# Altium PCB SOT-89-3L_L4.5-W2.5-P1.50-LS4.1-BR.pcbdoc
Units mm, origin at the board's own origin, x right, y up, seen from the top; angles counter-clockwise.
Board outline 18.08 x 17.35 mm, 2 copper layers (Top Layer, Bottom Layer), stack 0 mm thick; 1 components, 0 nets, 3 pads, 0 vias.
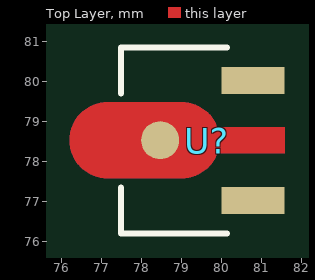
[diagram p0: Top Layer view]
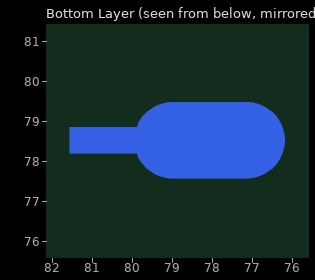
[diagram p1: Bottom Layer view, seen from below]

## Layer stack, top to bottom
Top Layer: signal copper (thickness not stored)
Bottom Layer: signal copper (thickness not stored)

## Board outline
87.927,69.85 69.85,69.85 69.85,87.202 87.927,87.202

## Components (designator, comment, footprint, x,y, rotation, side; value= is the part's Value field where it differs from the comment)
U? "" SOT-89-3L_L4.5-W2.5-P1.50-LS4.1-BR 79.433,78.526 r0 top

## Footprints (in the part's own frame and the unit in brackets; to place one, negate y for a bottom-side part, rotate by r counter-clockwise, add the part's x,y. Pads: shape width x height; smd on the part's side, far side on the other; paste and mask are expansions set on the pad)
SOT-89-3L_L4.5-W2.5-P1.50-LS4.1-BR [mm]
  rect 1.575x0.672 smd: 1(1.356,-1.5) 3(1.356,1.5)
  round 0.95 smd: 2(-0.966,0.009)
  Top Layer region: -2.283,0.959 -0.429,0.959 -0.384,0.958 -0.34,0.955 -0.296,0.949 -0.252,0.942 -0.208,0.933 -0.165,0.921 -0.123,0.908 -0.081,0.893 -0.04,0.875 0,0.856 0.04,0.835 0.078,0.812 0.115,0.788 0.151,0.761 0.185,0.733 0.219,0.704 0.251,0.673 0.281,0.64 0.31,0.606 0.337,0.571 0.362,0.534 0.386,0.497 0.408,0.458 0.428,0.418 0.447,0.339 2.144,0.339 2.144,-0.321 0.447,-0.321 0.428,-0.401 0.408,-0.44 0.386,-0.479 0.362,-0.517 0.337,-0.553 0.31,-0.588 0.281,-0.622 0.251,-0.655 0.219,-0.686 0.185,-0.716 0.151,-0.744 0.115,-0.77 0.078,-0.795 0.04,-0.818 0,-0.839 -0.04,-0.858 -0.081,-0.875 -0.123,-0.89 -0.165,-0.904 -0.208,-0.915 -0.252,-0.925 -0.296,-0.932 -0.34,-0.937 -0.384,-0.94 -0.429,-0.941 -2.283,-0.941 -2.328,-0.94 -2.372,-0.937 -2.416,-0.932 -2.46,-0.925 -2.504,-0.915 -2.547,-0.904 -2.589,-0.89 -2.631,-0.875 -2.672,-0.858 -2.713,-0.839 -2.752,-0.818 -2.79,-0.795 -2.827,-0.77 -2.863,-0.744 -2.898,-0.716 -2.931,-0.686 -2.963,-0.655 -2.993,-0.622 -3.022,-0.588 -3.049,-0.553 -3.075,-0.517 -3.098,-0.479 -3.12,-0.44 -3.141,-0.401 -3.159,-0.36 -3.175,-0.318 -3.189,-0.276 -3.202,-0.233 -3.212,-0.19 -3.22,-0.146 -3.227,-0.102 -3.231,-0.058 -3.233,-0.013 -3.233,0.031 -3.231,0.076 -3.227,0.12 -3.22,0.164 -3.212,0.208 -3.202,0.251 -3.189,0.294 -3.175,0.336 -3.159,0.377 -3.141,0.418 -3.12,0.458 -3.098,0.497 -3.075,0.534 -3.049,0.571 -3.022,0.606 -2.993,0.64 -2.963,0.673 -2.931,0.704 -2.898,0.733 -2.863,0.761 -2.827,0.788 -2.79,0.812 -2.752,0.835 -2.713,0.856 -2.672,0.875 -2.631,0.893 -2.589,0.908 -2.547,0.921 -2.504,0.933 -2.46,0.942 -2.416,0.949 -2.372,0.955 -2.328,0.958
  Bottom Layer region: -2.283,0.959 -0.429,0.959 -0.384,0.958 -0.34,0.955 -0.296,0.949 -0.252,0.942 -0.208,0.933 -0.165,0.921 -0.123,0.908 -0.081,0.893 -0.04,0.875 0,0.856 0.04,0.835 0.078,0.812 0.115,0.788 0.151,0.761 0.185,0.733 0.219,0.704 0.251,0.673 0.281,0.64 0.31,0.606 0.337,0.571 0.362,0.534 0.386,0.497 0.408,0.458 0.428,0.418 0.447,0.339 2.144,0.339 2.144,-0.321 0.447,-0.321 0.428,-0.401 0.408,-0.44 0.386,-0.479 0.362,-0.517 0.337,-0.553 0.31,-0.588 0.281,-0.622 0.251,-0.655 0.219,-0.686 0.185,-0.716 0.151,-0.744 0.115,-0.77 0.078,-0.795 0.04,-0.818 0,-0.839 -0.04,-0.858 -0.081,-0.875 -0.123,-0.89 -0.165,-0.904 -0.208,-0.915 -0.252,-0.925 -0.296,-0.932 -0.34,-0.937 -0.384,-0.94 -0.429,-0.941 -2.283,-0.941 -2.328,-0.94 -2.372,-0.937 -2.416,-0.932 -2.46,-0.925 -2.504,-0.915 -2.547,-0.904 -2.589,-0.89 -2.631,-0.875 -2.672,-0.858 -2.713,-0.839 -2.752,-0.818 -2.79,-0.795 -2.827,-0.77 -2.863,-0.744 -2.898,-0.716 -2.931,-0.686 -2.963,-0.655 -2.993,-0.622 -3.022,-0.588 -3.049,-0.553 -3.075,-0.517 -3.098,-0.479 -3.12,-0.44 -3.141,-0.401 -3.159,-0.36 -3.175,-0.318 -3.189,-0.276 -3.202,-0.233 -3.212,-0.19 -3.22,-0.146 -3.227,-0.102 -3.231,-0.058 -3.233,-0.013 -3.233,0.031 -3.231,0.076 -3.227,0.12 -3.22,0.164 -3.212,0.208 -3.202,0.251 -3.189,0.294 -3.175,0.336 -3.159,0.377 -3.141,0.418 -3.12,0.458 -3.098,0.497 -3.075,0.534 -3.049,0.571 -3.022,0.606 -2.993,0.64 -2.963,0.673 -2.931,0.704 -2.898,0.733 -2.863,0.761 -2.827,0.788 -2.79,0.812 -2.752,0.835 -2.713,0.856 -2.672,0.875 -2.631,0.893 -2.589,0.908 -2.547,0.921 -2.504,0.933 -2.46,0.942 -2.416,0.949 -2.372,0.955 -2.328,0.958
  Multi-Layer region: -2.283,0.959 -0.429,0.959 -0.384,0.958 -0.34,0.955 -0.296,0.949 -0.252,0.942 -0.208,0.933 -0.165,0.921 -0.123,0.908 -0.081,0.893 -0.04,0.875 0,0.856 0.04,0.835 0.078,0.812 0.115,0.788 0.151,0.761 0.185,0.733 0.219,0.704 0.251,0.673 0.281,0.64 0.31,0.606 0.337,0.571 0.362,0.534 0.386,0.497 0.408,0.458 0.428,0.418 0.447,0.339 2.144,0.339 2.144,-0.321 0.447,-0.321 0.428,-0.401 0.408,-0.44 0.386,-0.479 0.362,-0.517 0.337,-0.553 0.31,-0.588 0.281,-0.622 0.251,-0.655 0.219,-0.686 0.185,-0.716 0.151,-0.744 0.115,-0.77 0.078,-0.795 0.04,-0.818 0,-0.839 -0.04,-0.858 -0.081,-0.875 -0.123,-0.89 -0.165,-0.904 -0.208,-0.915 -0.252,-0.925 -0.296,-0.932 -0.34,-0.937 -0.384,-0.94 -0.429,-0.941 -2.283,-0.941 -2.328,-0.94 -2.372,-0.937 -2.416,-0.932 -2.46,-0.925 -2.504,-0.915 -2.547,-0.904 -2.589,-0.89 -2.631,-0.875 -2.672,-0.858 -2.713,-0.839 -2.752,-0.818 -2.79,-0.795 -2.827,-0.77 -2.863,-0.744 -2.898,-0.716 -2.931,-0.686 -2.963,-0.655 -2.993,-0.622 -3.022,-0.588 -3.049,-0.553 -3.075,-0.517 -3.098,-0.479 -3.12,-0.44 -3.141,-0.401 -3.159,-0.36 -3.175,-0.318 -3.189,-0.276 -3.202,-0.233 -3.212,-0.19 -3.22,-0.146 -3.227,-0.102 -3.231,-0.058 -3.233,-0.013 -3.233,0.031 -3.231,0.076 -3.227,0.12 -3.22,0.164 -3.212,0.208 -3.202,0.251 -3.189,0.294 -3.175,0.336 -3.159,0.377 -3.141,0.418 -3.12,0.458 -3.098,0.497 -3.075,0.534 -3.049,0.571 -3.022,0.606 -2.993,0.64 -2.963,0.673 -2.931,0.704 -2.898,0.733 -2.863,0.761 -2.827,0.788 -2.79,0.812 -2.752,0.835 -2.713,0.856 -2.672,0.875 -2.631,0.893 -2.589,0.908 -2.547,0.921 -2.504,0.933 -2.46,0.942 -2.416,0.949 -2.372,0.955 -2.328,0.958
  silkscreen extent -1.95,-2.33 0.7,2.33

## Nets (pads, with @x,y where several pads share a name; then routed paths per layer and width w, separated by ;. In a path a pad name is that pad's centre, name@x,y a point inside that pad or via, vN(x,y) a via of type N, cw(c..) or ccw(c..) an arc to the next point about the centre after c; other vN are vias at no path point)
pads on no net: U?.1 U?.2 U?.3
